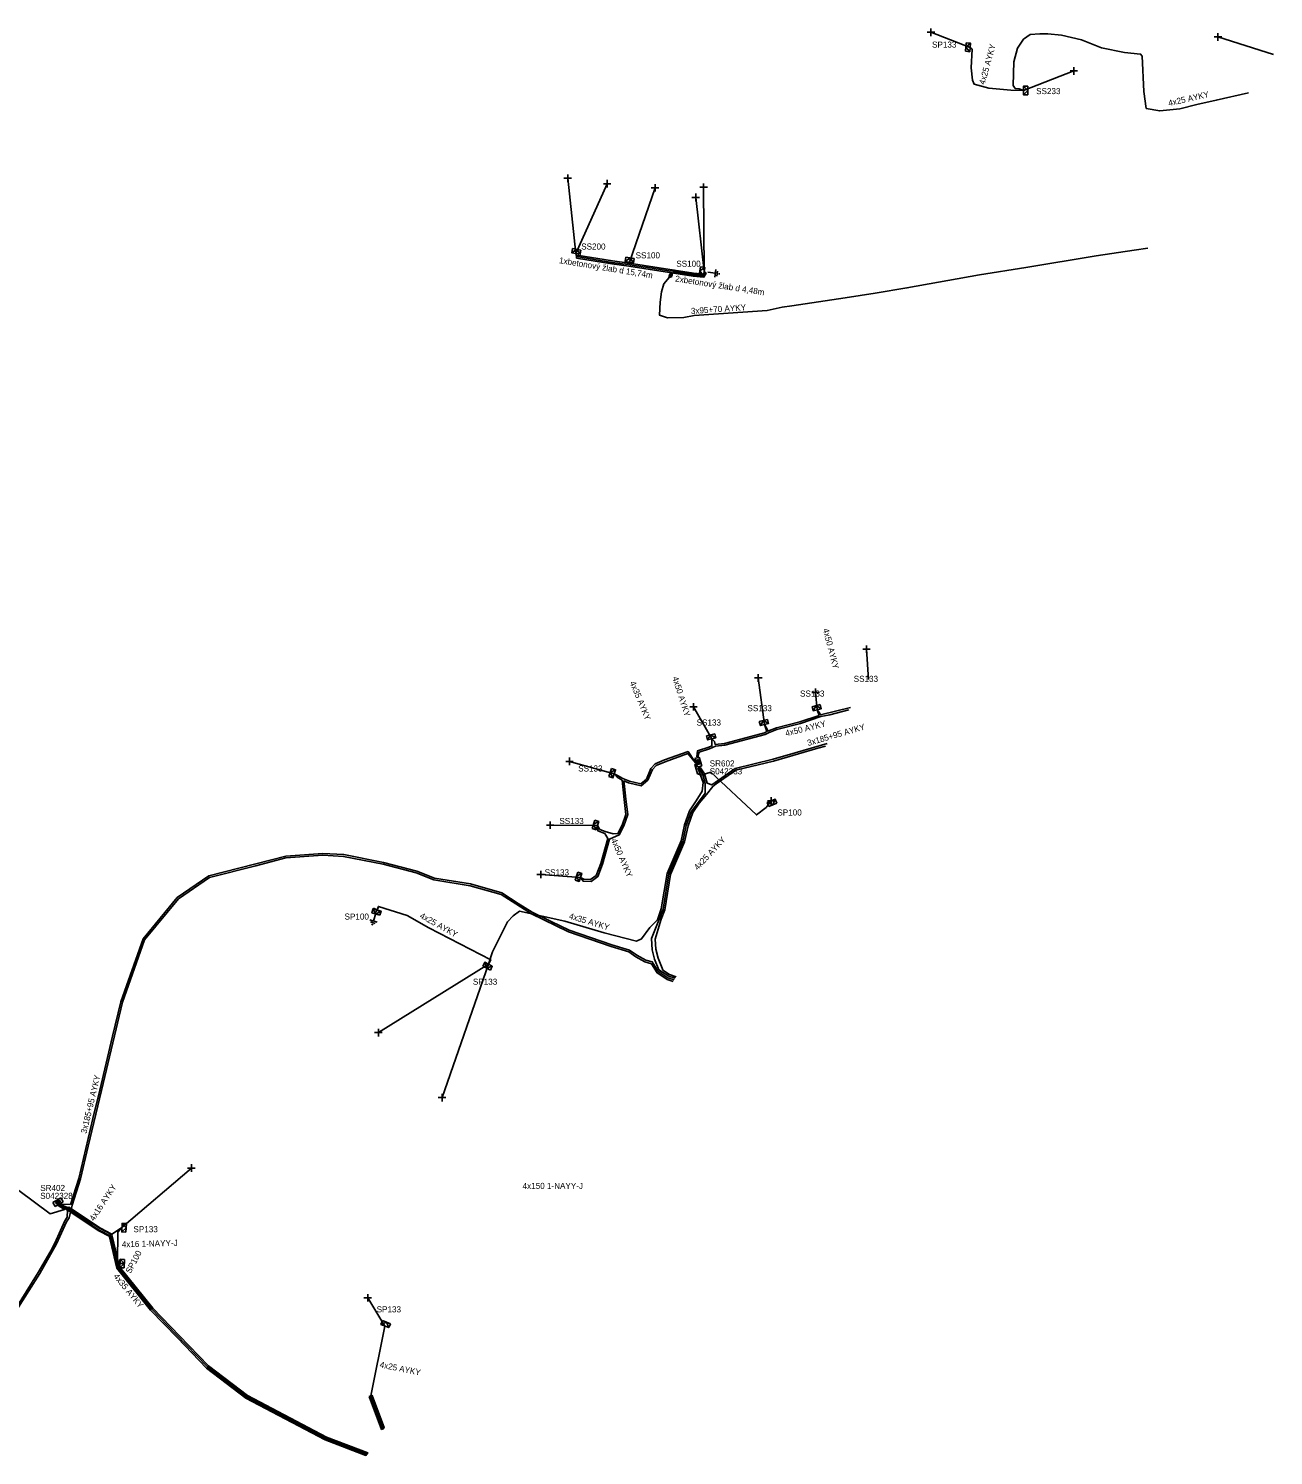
# Model space of a CAD drawing. Extents: x -737417 to -734469, y -1145580 to -1142703.
# Drawn here: x -736925.2 to -736720, y -1144914.8 to -1144679.8 of the extents above; entities that cross this region are included whole.
import ezdxf

# ---------------------------------------------------------------- set-up
doc = ezdxf.new("R2010")
doc.units = 0
for name, color, linetype in [('Vrstva 1', 7, 'Continuous'), ('Vrstva 14', 7, 'Continuous'), ('Vrstva 15', 7, 'Continuous'), ('Vrstva 19', 7, 'Continuous'), ('Vrstva 20', 7, 'Continuous'), ('Vrstva 21', 7, 'Continuous'), ('Vrstva 28', 7, 'Continuous'), ('Vrstva 29', 7, 'Continuous'), ('Vrstva 30', 7, 'Continuous'), ('Vrstva 31', 7, 'Continuous'), ('Vrstva 33', 7, 'Continuous'), ('Vrstva 34', 7, 'Continuous'), ('Vrstva 4', 7, 'Continuous'), ('Vrstva 5', 7, 'Continuous'), ('Vrstva 52', 7, 'Continuous'), ('Vrstva 54', 7, 'Continuous'), ('Vrstva 59', 7, 'Continuous'), ('Vrstva 6', 7, 'Continuous'), ('Vrstva 8', 7, 'Continuous'), ('Vrstva 9', 7, 'Continuous')]:
    doc.layers.add(name, color=color, linetype=linetype)

# ---------------------------------------------------------------- blocks, each defined once
blk = doc.blocks.new('NN870')
at = {"layer": 'Vrstva 4'}
for points in [[(0, -0.25), (0.5, 0), (0, 0.25), (-0.5, 0), (0, -0.25)], [(0.37, 0), (0, 0.19), (-0.36, 0), (0, -0.19), (0.37, 0)], [(0.24, 0), (0, 0.12), (-0.25, 0), (0, -0.12), (0.24, 0)], [(0.12, 0), (0, 0.06), (-0.13, 0), (0, -0.06), (0.12, 0)]]:
    blk.add_lwpolyline(points, dxfattribs=at)
blk = doc.blocks.new('NN800')
at = {"layer": 'Vrstva 1'}
for points in [[(-0.44, 0.44), (0.44, -0.44)], [(-0.44, -0.44), (0.44, 0.44)]]:
    blk.add_lwpolyline(points, dxfattribs=at)
blk = doc.blocks.new('NN620')
at = {"layer": 'Vrstva 8'}
for points in [[(0.75, 0), (-0.75, 0)], [(-0.75, 0), (-0.75, -0.75)], [(0.75, -0.75), (0.75, 0)], [(-0.75, -0.75), (0.75, -0.75)], [(0.37, -0.18), (-0.38, -0.18)], [(-0.38, -0.18), (-0.38, -0.56)], [(-0.38, -0.56), (0.37, -0.56)], [(0.32, -0.23), (-0.33, -0.23)], [(-0.33, -0.23), (-0.33, -0.51)], [(-0.33, -0.51), (0.32, -0.51)], [(0.27, -0.27), (-0.28, -0.27)], [(-0.28, -0.27), (-0.28, -0.46)], [(-0.28, -0.46), (0.27, -0.46)], [(0.23, -0.32), (-0.23, -0.32)], [(-0.23, -0.32), (-0.23, -0.42)], [(-0.23, -0.42), (0.23, -0.42)], [(-0.19, -0.37), (0.19, -0.37)], [(0.23, -0.42), (0.23, -0.32)], [(0.27, -0.46), (0.27, -0.27)], [(0.32, -0.51), (0.32, -0.23)], [(0.37, -0.56), (0.37, -0.18)]]:
    blk.add_lwpolyline(points, dxfattribs=at)
blk = doc.blocks.new('NN630')
at = {"layer": 'Vrstva 9'}
for points in [[(0, -0.7), (-0.7, 0)], [(-0.7, -0.7), (-0.7, 0), (0.7, 0), (0.7, -0.7)], [(-0.7, -0.7), (0.7, -0.7)], [(0, -0.7), (0.7, 0)]]:
    blk.add_lwpolyline(points, dxfattribs=at)
blk = doc.blocks.new('NN810')
at = {"layer": 'Vrstva 14'}
for points in [[(0.63, -1.89), (-0.62, -1.89)], [(0.39, -2.2), (-0.4, -2.2)], [(0, -0.64), (0, -1.89)], [(0, -2.52), (-0.12, -2.52)], [(0.14, -2.52), (0, -2.52)]]:
    blk.add_lwpolyline(points, dxfattribs=at)

msp = doc.modelspace()

# ---------------------------------------------------------------- linework, layer by layer
at = {"layer": 'Vrstva 20'}
for points in [[(-736834.86, -1144717.57), (-736834.78, -1144717.07), (-736828.93, -1144718.03), (-736826.15, -1144718.39), (-736818.73, -1144719.56), (-736818.81, -1144720.06), (-736826.22, -1144718.89), (-736829.02, -1144718.53)], [(-736818.81, -1144720.06), (-736818.73, -1144719.56), (-736815.55, -1144720.06), (-736813.82, -1144720.23), (-736813.86, -1144720.73), (-736815.62, -1144720.56)], [(-736911.76, -1144878.75), (-736913.55, -1144877.81), (-736918.77, -1144874.35), (-736918.49, -1144873.93), (-736913.29, -1144877.38), (-736911.52, -1144878.31)], [(-736911.88, -1144878.59), (-736911.4, -1144878.47), (-736910.16, -1144883.78), (-736904.66, -1144890.55), (-736900.26, -1144895.14), (-736895.5, -1144900.06), (-736889.06, -1144904.99), (-736876.06, -1144911.83), (-736869.26, -1144914.41), (-736869.54, -1144914.84), (-736876.26, -1144912.29), (-736889.33, -1144905.41), (-736895.84, -1144900.44), (-736900.62, -1144895.49), (-736905.04, -1144890.89), (-736910.62, -1144884)], [(-736868.99, -1144905.13), (-736868.53, -1144904.95), (-736866.55, -1144910.24), (-736866.69, -1144910.46), (-736866.96, -1144910.56)]]:
    msp.add_lwpolyline(points, close=True, dxfattribs=at)
at = {"layer": 'Vrstva 5'}
for points in [[(-736761.19, -1144689.96), (-736761.89, -1144689.69), (-736762.53, -1144689.66), (-736762.9, -1144689.16), (-736762.8, -1144685.25), (-736762.17, -1144683.01), (-736761.2, -1144681.53), (-736760.09, -1144680.75), (-736758.47, -1144680.61), (-736757.15, -1144680.65), (-736754.94, -1144680.82), (-736751.63, -1144681.59), (-736748.35, -1144682.95), (-736744.53, -1144683.71), (-736741.89, -1144683.96), (-736741.6, -1144684.29), (-736741.34, -1144690.13), (-736740.94, -1144692.92), (-736738.72, -1144693.32), (-736735.44, -1144693.01), (-736732.61, -1144692.27), (-736729.41, -1144691.58), (-736724.1, -1144690.37)], [(-736740.67, -1144715.94), (-736742.94, -1144716.28), (-736749.18, -1144717.2), (-736760.82, -1144719.13), (-736768.43, -1144720.36), (-736780.4, -1144722.49), (-736785.6, -1144723.35), (-736790.55, -1144724.14), (-736799.36, -1144725.44), (-736800.97, -1144725.67), (-736803.45, -1144726.21), (-736815.48, -1144727.06), (-736817.13, -1144727.35), (-736819.87, -1144727.44), (-736821.19, -1144726.97), (-736821.08, -1144724.85), (-736820.85, -1144723.12), (-736820.44, -1144721.83), (-736819.32, -1144720.43)], [(-736819.32, -1144720.43), (-736818.85, -1144719.9), (-736815.59, -1144720.41), (-736813.78, -1144720.59), (-736813.5, -1144720.07), (-736813.83, -1144719.79), (-736813.74, -1144720.09), (-736813.9, -1144720.37), (-736815.57, -1144720.21), (-736819.05, -1144719.66), (-736819.3, -1144719.73), (-736822.37, -1144719.24), (-736826.08, -1144718.66), (-736826.13, -1144718.23), (-736826.28, -1144718.63), (-736827.27, -1144718.5), (-736828.97, -1144718.28), (-736834.82, -1144717.32), (-736834.93, -1144716.82)], [(-736815.01, -1144799.75), (-736814.88, -1144798.74), (-736813.01, -1144798.15), (-736812.53, -1144797.95), (-736812.56, -1144796.79), (-736812.12, -1144797.24), (-736812.01, -1144797.7), (-736810.46, -1144797.52), (-736803.88, -1144795.8), (-736803.46, -1144795.59), (-736803.87, -1144794.42), (-736803.4, -1144795.16), (-736803.3, -1144795.51), (-736801.91, -1144794.97), (-736798.03, -1144793.99), (-736794.88, -1144792.92), (-736795.18, -1144791.99), (-736794.78, -1144792.52), (-736794.66, -1144792.82), (-736789.69, -1144791.61)], [(-736789.94, -1144791.99), (-736793.1, -1144792.81), (-736794.6, -1144793.12), (-736797.95, -1144794.27), (-736801.81, -1144795.25), (-736803.19, -1144795.79), (-736803.78, -1144796.08), (-736810.4, -1144797.82), (-736811.93, -1144798), (-736812.91, -1144798.43), (-736814.62, -1144798.98), (-736814.84, -1144799.7)], [(-736818.44, -1144835.97), (-736819.5, -1144835.6), (-736820.64, -1144834.89), (-736820.75, -1144834.55), (-736821.41, -1144832.93), (-736821.75, -1144831.43), (-736821.88, -1144829.77), (-736820.88, -1144826.49), (-736820.3, -1144824.94), (-736819.34, -1144819.13), (-736817.02, -1144813.76), (-736816.46, -1144811.11), (-736815.7, -1144808.93), (-736814.62, -1144807.37), (-736813.43, -1144805.94), (-736812.39, -1144804.61), (-736811.81, -1144804.21), (-736808.57, -1144801.94), (-736802.38, -1144800.43), (-736795.09, -1144798.34), (-736793.81, -1144797.96)], [(-736814.5, -1144801.44), (-736814.39, -1144801.56), (-736813.75, -1144802.56), (-736813.33, -1144804.08), (-736812.57, -1144804.37), (-736808.69, -1144801.66), (-736802.46, -1144800.14), (-736798.83, -1144799.08), (-736793.54, -1144797.55)], [(-736834.2, -1144819.61), (-736833.64, -1144819.92), (-736832.52, -1144819.96), (-736831.58, -1144819.28), (-736830.86, -1144817.3), (-736829.67, -1144813.22), (-736830.2, -1144812.35), (-736831.32, -1144811.94), (-736831.4, -1144811.08), (-736831, -1144811.69), (-736830.12, -1144812.06), (-736828.79, -1144812.42), (-736828.02, -1144812.39), (-736827.33, -1144810.98), (-736826.71, -1144809.22), (-736827.01, -1144806.77), (-736827.33, -1144803.6), (-736828.16, -1144803.12), (-736828.63, -1144802.55), (-736827.98, -1144802.88), (-736827.2, -1144803.33), (-736826.13, -1144803.76), (-736824.25, -1144804.18), (-736823.33, -1144803.4), (-736822.6, -1144801.68), (-736821.88, -1144800.9), (-736820.32, -1144800.26), (-736816.47, -1144798.89), (-736815.3, -1144800.62)], [(-736834.2, -1144819.61), (-736833.76, -1144820.22), (-736832.42, -1144820.26), (-736831.33, -1144819.46), (-736830.58, -1144817.4), (-736829.39, -1144813.3), (-736827.81, -1144812.62), (-736827.05, -1144811.1), (-736826.41, -1144809.26), (-736826.71, -1144806.73), (-736826.91, -1144804.63), (-736827.06, -1144803.71), (-736826.25, -1144804.04), (-736824.17, -1144804.5), (-736823.09, -1144803.58), (-736822.34, -1144801.84), (-736821.7, -1144801.16), (-736820.22, -1144800.54), (-736816.49, -1144799.21), (-736815.26, -1144800.75)], [(-736814.84, -1144801.54), (-736813.96, -1144803.98), (-736814.12, -1144805.39), (-736815.1, -1144807.01), (-736816.24, -1144808.65), (-736817.05, -1144810.95), (-736817.59, -1144813.57), (-736819.93, -1144818.96), (-736820.89, -1144824.78), (-736821.52, -1144826.58), (-736822.74, -1144827.88), (-736824.11, -1144829.72), (-736824.95, -1144830.1), (-736830.27, -1144828.73), (-736836.75, -1144826.8), (-736844.22, -1144825.19), (-736845.29, -1144825.93), (-736846.21, -1144826.91), (-736848.67, -1144831.87), (-736849.34, -1144833.92)], [(-736818.6, -1144836.23), (-736819.64, -1144835.88), (-736821.25, -1144834.85), (-736821.98, -1144833.1), (-736822.35, -1144831.52), (-736822.48, -1144829.7), (-736821.17, -1144826.4), (-736820.59, -1144824.86), (-736819.64, -1144819.04), (-736817.31, -1144813.67), (-736816.76, -1144811.03), (-736815.97, -1144808.79), (-736813.66, -1144805.75), (-736813.62, -1144804.16), (-736814.03, -1144802.69), (-736814.7, -1144801.5)], [(-736927.44, -1144891.48), (-736925.09, -1144887.72), (-736923.3, -1144884.88), (-736920.53, -1144880), (-736918.91, -1144876.33), (-736918.46, -1144875.67), (-736917.97, -1144873.59), (-736916.58, -1144869.29), (-736915.3, -1144863.87), (-736913.12, -1144854.71), (-736909.64, -1144840.18), (-736906.02, -1144829.87), (-736900.43, -1144823.15), (-736895.31, -1144819.64), (-736887.68, -1144817.7), (-736882.73, -1144816.41), (-736876.65, -1144815.95), (-736873.23, -1144816.14), (-736866.72, -1144817.45), (-736861.25, -1144818.86), (-736858.35, -1144820.02), (-736852.36, -1144820.97), (-736847.27, -1144822.45), (-736842.27, -1144825.62), (-736836.16, -1144828.58), (-736829.15, -1144831), (-736826.24, -1144831.89), (-736825.08, -1144832.68), (-736823.56, -1144833.52), (-736822.49, -1144833.82), (-736821.57, -1144835.35), (-736819.9, -1144836.42), (-736818.94, -1144836.75)], [(-736818.77, -1144836.49), (-736819.77, -1144836.15), (-736821.41, -1144835.1), (-736822.35, -1144833.54), (-736823.44, -1144833.24), (-736824.92, -1144832.42), (-736826.11, -1144831.61), (-736829.05, -1144830.72), (-736836.04, -1144828.3), (-736839.03, -1144826.87), (-736842.13, -1144825.36), (-736844.48, -1144823.9), (-736847.15, -1144822.17), (-736852.3, -1144820.67), (-736858.27, -1144819.72), (-736861.15, -1144818.58), (-736866.66, -1144817.15), (-736873.19, -1144815.84), (-736876.65, -1144815.65), (-736882.77, -1144816.11), (-736895.43, -1144819.36), (-736900.63, -1144822.93), (-736906.28, -1144829.73), (-736909.92, -1144840.1), (-736911.31, -1144845.78), (-736913.42, -1144854.65), (-736914.54, -1144859.34), (-736916.86, -1144869.21), (-736918.25, -1144873.49), (-736919.81, -1144873.43)], [(-736933.7, -1144864.52), (-736934.04, -1144865.07), (-736934.19, -1144865.71), (-736931.73, -1144867.53), (-736921.6, -1144875.04), (-736919.22, -1144874.32), (-736920.26, -1144873.68)], [(-736931.98, -1144898.17), (-736923.56, -1144884.72), (-736921.5, -1144881.12), (-736920.79, -1144879.86), (-736919.17, -1144876.19), (-736918.76, -1144875.57), (-736918.71, -1144874.43), (-736920.15, -1144873.61)], [(-736920.03, -1144873.57), (-736918.41, -1144874.39), (-736913.5, -1144877.73), (-736911.6, -1144878.72), (-736910.39, -1144883.89), (-736904.85, -1144890.72), (-736900.88, -1144894.85), (-736895.67, -1144900.25), (-736889.19, -1144905.2), (-736882.97, -1144908.49), (-736876.16, -1144912.06), (-736869.4, -1144914.63)]]:
    msp.add_lwpolyline(points, dxfattribs=at)
at = {"layer": 'Vrstva 52'}
for points in [[(-736761.19, -1144689.96), (-736763.25, -1144689.91), (-736766.9, -1144689.6), (-736769.29, -1144688.94), (-736769.6, -1144688.28), (-736769.81, -1144686.21), (-736769.65, -1144683.18), (-736769.97, -1144682.87)], [(-736815.23, -1144800.87), (-736815.32, -1144801.02), (-736814.89, -1144802.53), (-736814.3, -1144802.74), (-736812.7, -1144802.29), (-736805.2, -1144809.31), (-736803.61, -1144808.08), (-736802.75, -1144807)], [(-736849.34, -1144833.92), (-736848.95, -1144833.19), (-736859.16, -1144827.89), (-736862.76, -1144825.89), (-736867.49, -1144824.39), (-736867.72, -1144824.97)], [(-736919.92, -1144873.49), (-736918.55, -1144874.02), (-736913.34, -1144877.47), (-736911.49, -1144878.44), (-736909.76, -1144877.31)], [(-736909.76, -1144877.31), (-736910.41, -1144878.05), (-736910.48, -1144882.96), (-736910.08, -1144883.23)], [(-736866.72, -1144910.5), (-736866.73, -1144910.47), (-736868.76, -1144905.04), (-736866.43, -1144893.52)]]:
    msp.add_lwpolyline(points, dxfattribs=at)
at = {"layer": 'Vrstva 59'}
for points in [[(-736769.97, -1144682.87), (-736776.44, -1144680.38)], [(-736719.99, -1144684.02), (-736729.14, -1144681.14)], [(-736761.19, -1144689.96), (-736752.88, -1144686.75)], [(-736834.93, -1144716.82), (-736836.3, -1144704.4)], [(-736834.93, -1144716.82), (-736829.8, -1144705.33)], [(-736826.13, -1144718.23), (-736821.9, -1144706)], [(-736813.83, -1144719.79), (-736813.9, -1144705.9)], [(-736813.83, -1144719.79), (-736815.2, -1144707.58)], [(-736786.7, -1144786.99), (-736787.06, -1144782)], [(-736803.87, -1144794.42), (-736804.88, -1144786.75)], [(-736795.18, -1144791.99), (-736795.44, -1144789.13)], [(-736812.56, -1144796.79), (-736815.56, -1144791.5)], [(-736828.63, -1144802.55), (-736836, -1144800.5)], [(-736831.4, -1144811.08), (-736839.19, -1144811)], [(-736834.2, -1144819.61), (-736840.75, -1144819.13)], [(-736849.34, -1144833.92), (-736867.5, -1144845.18)], [(-736849.34, -1144833.92), (-736857, -1144855.88)], [(-736909.76, -1144877.31), (-736898.31, -1144867.5)], [(-736866.43, -1144893.52), (-736869.25, -1144888.88)]]:
    msp.add_lwpolyline(points, dxfattribs=at)

# ---------------------------------------------------------------- block references
at = {"layer": 'Vrstva 15'}
for p, rotation in [((-736813.83, -1144719.79), 81.02812497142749), ((-736867.72, -1144824.97), -17.891844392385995)]:
    msp.add_blockref('NN810', p, dxfattribs=dict(at, rotation=rotation))
at = {"layer": 'Vrstva 19', "rotation": 51.340191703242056}
msp.add_blockref('NN870', (-736819.32, -1144720.43), dxfattribs=at)
at = {"layer": 'Vrstva 28'}
for p, rotation in [((-736815.14, -1144800.71), 106.85840001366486), ((-736920.1, -1144873.44), -150.66816102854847)]:
    msp.add_blockref('NN620', p, dxfattribs=dict(at, rotation=rotation))
at = {"layer": 'Vrstva 31'}
for p, rotation in [((-736769.97, -1144682.87), -95.11401381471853), ((-736761.19, -1144689.96), 90), ((-736834.93, -1144716.82), 170.3512973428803), ((-736826.13, -1144718.23), 170.3512972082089), ((-736813.83, -1144719.79), -98.97187496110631), ((-736795.18, -1144791.99), -165.73548888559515), ((-736803.87, -1144794.42), -165.50768057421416), ((-736812.56, -1144796.79), -165.2089139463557), ((-736828.63, -1144802.55), -108.17965554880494), ((-736802.75, -1144807), 22.50644989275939), ((-736831.4, -1144811.08), -108.21709443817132), ((-736834.2, -1144819.61), -108.179655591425), ((-736867.72, -1144824.97), -17.374174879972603), ((-736849.34, -1144833.92), -27.65834993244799), ((-736909.76, -1144877.31), 86.8655888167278), ((-736910.08, -1144883.22), 88.4995472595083), ((-736866.43, -1144893.52), 158.03352497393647)]:
    msp.add_blockref('NN630', p, dxfattribs=dict(at, rotation=rotation))
at = {"layer": 'Vrstva 34'}
for p, rotation in [((-736776.44, -1144680.38), 44.99999995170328), ((-736729.14, -1144681.14), -135), ((-736752.88, -1144686.75), 45), ((-736836.3, -1144704.4), 45), ((-736829.8, -1144705.33), 45), ((-736821.9, -1144706), 45), ((-736813.9, -1144705.9), 45), ((-736815.2, -1144707.58), 44.99999995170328), ((-736787.06, -1144782), 45), ((-736804.88, -1144786.75), 45), ((-736795.44, -1144789.13), 44.99999995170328), ((-736815.56, -1144791.5), 45), ((-736836, -1144800.5), 45), ((-736802.75, -1144807), 44.99999995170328), ((-736839.19, -1144811), 44.99999995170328), ((-736840.75, -1144819.13), 45), ((-736867.72, -1144824.97), -72.31158891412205), ((-736867.5, -1144845.18), 45), ((-736857, -1144855.88), 45), ((-736898.31, -1144867.5), 45), ((-736910.08, -1144883.23), 45), ((-736869.25, -1144888.88), 45)]:
    msp.add_blockref('NN800', p, dxfattribs=dict(at, rotation=rotation))

# ---------------------------------------------------------------- texts
at = {"layer": 'Vrstva 21'}
for s, rotation, p in [('1xbetonový žlab d 15,74m', 350.682, (-736837.77, -1144718.4)), ('2xbetonový žlab d 4,48m', 351.093, (-736818.64, -1144721.42))]:
    msp.add_text(s, height=1, rotation=rotation, dxfattribs=at).set_placement(p)
at = {"layer": 'Vrstva 29'}
for s, p in [('S042333', (-736812.89, -1144802.63)), ('S042328', (-736923.22, -1144872.57))]:
    msp.add_text(s, height=1, dxfattribs=at).set_placement(p)
at = {"layer": 'Vrstva 30'}
for s, p in [('SR602', (-736812.89, -1144801.33)), ('SR402', (-736923.22, -1144871.27))]:
    msp.add_text(s, height=1, dxfattribs=at).set_placement(p)
at = {"layer": 'Vrstva 33'}
for s, p in [('SP133', (-736776.25, -1144682.9)), ('SS233', (-736759.1, -1144690.56)), ('SS200', (-736834.07, -1144716.17)), ('SS100', (-736825.1, -1144717.62)), ('SS100', (-736818.4, -1144719)), ('SS133', (-736789.16, -1144787.39)), ('SS133', (-736798, -1144789.82)), ('SS133', (-736806.67, -1144792.22)), ('SS133', (-736815.05, -1144794.59)), ('SS133', (-736834.57, -1144802.16)), ('SS133', (-736837.67, -1144810.81)), ('SP100', (-736801.74, -1144809.41)), ('SS133', (-736840.09, -1144819.27)), ('SP100', (-736873.07, -1144826.56)), ('SP133', (-736851.92, -1144837.29)), ('SP133', (-736907.86, -1144878.06)), ('SP133', (-736867.78, -1144891.27))]:
    msp.add_text(s, height=1, dxfattribs=at).set_placement(p)
msp.add_text('SP100', height=1, rotation=61.699, dxfattribs=at).set_placement((-736908.35, -1144884.96))
at = {"layer": 'Vrstva 54'}
for s, rotation, p in [('4x25 AYKY', 74.562, (-736767.57, -1144689.07)), ('4x25 AYKY', 46.893, (-736814.87, -1144818.49)), ('4x25 AYKY', 330.945, (-736860.78, -1144826.22)), ('4x16 AYKY', 56.407, (-736914.37, -1144876.31)), ('4x16 1-NAYY-J', 1.62, (-736909.77, -1144880.57)), ('4x25 AYKY', 348.566, (-736867.34, -1144900.33))]:
    msp.add_text(s, height=1, rotation=rotation, dxfattribs=at).set_placement(p)
at = {"layer": 'Vrstva 6'}
for s, rotation, p in [('4x25 AYKY', 12.845, (-736737.2, -1144692.55)), ('3x95+70 AYKY', 4.042, (-736815.96, -1144726.8)), ('4x50 AYKY', 284.541, (-736794.26, -1144778.72)), ('4x35 AYKY', 292.51, (-736826.1, -1144787.51)), ('4x50 AYKY', 287.658, (-736819.07, -1144786.69)), ('4x50 AYKY', 14.207, (-736800.3, -1144796.38)), ('3x185+95 AYKY', 16.171, (-736796.67, -1144797.97)), ('4x50 AYKY', 293.439, (-736829.19, -1144813.44)), ('4x35 AYKY', 343.414, (-736836.16, -1144826.39)), ('3x185+95 AYKY', 76.502, (-736915.6, -1144861.88)), ('4x35 AYKY', 309.046, (-736911.22, -1144885.37))]:
    msp.add_text(s, height=1, rotation=rotation, dxfattribs=at).set_placement(p)
msp.add_text('4x150 1-NAYY-J', height=1, dxfattribs=at).set_placement((-736843.73, -1144870.93))

doc.saveas('drawing.dxf')
